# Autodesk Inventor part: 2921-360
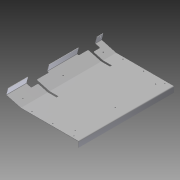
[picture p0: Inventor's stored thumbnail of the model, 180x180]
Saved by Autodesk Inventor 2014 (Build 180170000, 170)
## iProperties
Company: NHTSA/VRTC
Created: 2012-02
Part Number: 2921-360
Project: CHILD SIDE IMPACT SLED
Material: Steel
Description: BENCH SEAT PANEL
Document SubType Name: Modeling
Designer: Mike Vanvoorhis
Mass: 10084.5 g
Surface Area: 8157.07 cm^2
Volume: 1284.64 cm^3
Density: 7.85 g/cm^3
Appearance: Steel
Stock Number: PL 3.2 (1/8") x 614.5 (24 3/16") x 693 (27 5/16")
Title: Bench Seat Panel
Subject: Child Side Impact Sled
Author: Dave Walker
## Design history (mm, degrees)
sketch "Sketch1"
  geometry: L1 (417.373, -41)-(420.573, -41); L2 (420.573, -41)-(420.573, -6.4); L3 (417.373, -6.4)-(417.373, -41); L4 (-0.427, -3.2)-(414.173, -3.2); L5 (0, 0)-(-102.941, 27.969); L6 (-105.19, 31.896)-(-93.759, 73.97); L7 (-93.759, 73.97)-(-96.847, 74.809); L8 (-96.847, 74.809)-(-108.278, 32.735); L9 (-103.78, 24.88)-(-0.427, -3.2); L10 (414.173, 0)-(0, 0); L11 (0, 97.971)-(0, -64.162) reference; L12 (-216.266, 0)-(528.259, 0) reference; A1 r 3.2 centre (-102.102, 31.057) between (-105.19, 31.896) and (-102.941, 27.969); A2 r 3.2 centre (414.173, -6.4) between (417.373, -6.4) and (414.173, -3.2); A3 r 6.4 centre (414.173, -6.4) between (420.573, -6.4) and (414.173, 0); A4 r 6.4 centre (-102.102, 31.057) between (-108.278, 32.735) and (-103.78, 24.88); 1 further point
  constraints: 20 end point, 8 point on circle, 8 tangent, 5 parallel, 4 centre point, 3 point on line, 2 equal radius, 2 horizontal, 2 perpendicular, 1 collinear
  dimensions: "d0" = 3.2 distance of L1.start L1.end; "d2" = 3.2 distance between parallel lines of L10 L4 (= d0); "d3" = 15.2 deg angle of L9 L4; "d4" = 3.2 distance between parallel lines of L9 L5 (= d0); "d5" = 3.2 distance between parallel lines of L6 L8 (= d0); "d6" = 41 distance between parallel lines of L1 L10; "d7" = 421 distance from line of L4.start L2; "d8" = 113.5 distance from line of L4.start L8; "d9" = 50 distance between parallel lines of L7 L9; "d11" = 6.4 radius of A3; "d48" = 3.2 radius of A1
extrude "Extrusion1" new body sketch "Sketch1" stored distance "d12" = 693; taper "d13" = 0 deg
sketch "Sketch2"
  geometry: L1 (-3.2, 693)-(-3.2, 0) reference; L2 (-3.2, 598)-(171.8, 598); L3 (171.8, 598)-(171.8, 584); L4 (171.8, 584)-(-3.2, 584); L5 (-3.2, 584)-(-3.2, 598); L6 (-3.2, 209)-(171.8, 209); L7 (171.8, 209)-(171.8, 195); L8 (171.8, 195)-(-3.2, 195); L9 (-3.2, 195)-(-3.2, 209); 1 further point
  constraints: 16 end point, 4 parallel, 2 horizontal, 2 perpendicular, 2 point on line, 1 collinear
  dimensions: "d14" = 95 distance from line of L2 L1.start; "d15" = 14 distance between parallel lines of L4 L2; "d16" = 375 distance between parallel lines of L6 L4; "d17" = 14 distance between parallel lines of L8 L6 (= d15); "d18" = 175 distance between parallel lines of L3 L1
extrude "Extrusion2" cut sketch "Sketch2" stored distance "d19" = 700; taper "d20" = 0 deg
sketch "Sketch3"
  geometry: L1 (0, 0)-(414.173, 0) reference; L2 (420.573, 693)-(420.573, 0) reference; L3 (420.573, 693)-(420.573, 0) reference; 11 further points
  constraints: 5 vertical alignment, 4 horizontal alignment
  dimensions: "d25" = 15.5 distance from line of point (369.673, 15.5) L1; "d105" = 54 distance from line of point (340.573, 54) L1; "d106" = 346.5 distance from line of point (340.573, 346.5) L1; "d107" = 639 distance from line of point (340.573, 639) L1; "d108" = 677.5 distance from line of point (369.673, 677.5) L1; "d109" = 50.9 distance from line of point (369.673, 15.5) L2; "d110" = 205 distance from line of point (215.573, 15.5) L2; "d111" = 356 distance from line of point (64.573, 15.5) L2; "d112" = 80 distance from line of point (340.573, 639) L2
hole "Hole1" sketch "Sketch3" at (369.673, 15.5), (340.573, 54), (215.573, 15.5), (64.573, 15.5), (340.573, 346.5), (369.673, 677.5), (340.573, 639), (215.573, 677.5), (64.573, 677.5) diameter "d30" = 7.1374; stored, may be unused: countersink angle "d34" = 90 deg, drill point angle "d36" = 118 deg; dims "d31" = 6, "d32" = 4, "d33" = 2, "d35" = 8
sketch "Sketch4"
  geometry: L1 (195, 0)-(195, 43.6) reference; L2 (-498, 43.6)-(-498, 0) reference; L3 (0, 43.6)-(195, 43.6) reference; 7 further points; 4 other entities
  constraints: 2 vertical alignment, 1 horizontal alignment, 4 other
  dimensions: "d39" = 15 distance from line of point (179.5, 28.6) L3
hole "Hole2" sketch "Sketch4" at (179.5, 28.6), (-482.5, 28.6) diameter "d40" = 7.1374; stored, may be unused: countersink angle "d44" = 90 deg, drill point angle "d46" = 118 deg; dims "d41" = 6, "d42" = 4, "d43" = 2, "d45" = 3.2
fillet "Fillet1" dims "d49" = 5.76
fillet "Fillet2" dims "d50" = 7.94
sketch "Sketch17"
  geometry: L1 (0, 195)-(40, 195); L2 (40, 195)-(40, 145); L3 (40, 145)-(0, 145); L4 (0, 145)-(0, 195); 2 further points
  constraints: 8 end point, 2 parallel, 1 horizontal, 1 perpendicular
  dimensions: "d88" = 145 distance from line of L3 point (0, 0); "d89" = 40 distance of L2.end L3.end
extrude "Extrusion15" cut sketch "Sketch17" stored distance "d91" = 10; taper "d92" = 0 deg
sketch "Sketch18"
  geometry: L1 (-3.2, 375)-(-3.2, 0) reference; L2 (-3.2, 0)-(11.8, 0); L3 (11.8, 0)-(11.8, 90); L4 (11.8, 90)-(-3.2, 90); L5 (-3.2, 90)-(-3.2, 0); 1 further point
  constraints: 8 end point, 2 parallel, 1 horizontal, 1 perpendicular
  dimensions: "d93" = 90 distance from line of L4 L1.end; "d94" = 15 distance between parallel lines of L3 L1
extrude "Extrusion16" cut sketch "Sketch18" stored distance "d95" = 10; taper "d96" = 0 deg
sketch "Sketch19"
  geometry: L1 (-3.2, 95)-(-3.2, 0) reference; L2 (-3.2, 0)-(36.8, 0); L3 (36.8, 0)-(36.8, 50); L4 (36.8, 50)-(-3.2, 50); L5 (-3.2, 50)-(-3.2, 0); 1 further point
  constraints: 8 end point, 2 parallel, 1 horizontal, 1 perpendicular
  dimensions: "d97" = 45 distance from line of L4 L1.start; "d98" = 40 distance between parallel lines of L3 L1
extrude "Extrusion17" cut sketch "Sketch19" stored distance "d99" = 10; taper "d100" = 0 deg
sketch "Sketch20"
  geometry: L1 (-3.2, 285)-(-3.2, 0) reference; L2 (-3.2, 285)-(11.8, 285); L3 (11.8, 285)-(11.8, 215); L4 (11.8, 215)-(-3.2, 215); L5 (-3.2, 215)-(-3.2, 285); L6 (109.104, 285)-(3.2, 285) reference; 1 further point
  constraints: 8 end point, 2 parallel, 1 horizontal, 1 perpendicular
  dimensions: "d101" = 70 distance between parallel lines of L4 L6; "d102" = 15 distance between parallel lines of L3 L1
extrude "Extrusion18" cut sketch "Sketch20" stored distance "d103" = 0; taper "d104" = 0 deg
fillet "Fillet3" dims "d113" = 6
sketch "Sketch21"
  geometry: L1 (-109.104, 0)-(-109.104, 145) reference; 7 further points; 3 other entities
  constraints: 3 horizontal alignment, 2 vertical alignment, 3 other
  dimensions: "d114" = 68.5 distance from line of point (-40.604, 54) L1
hole "Hole3" sketch "Sketch21" at (-40.604, 54), (-40.604, 639), (-40.604, 346.5) diameter "d115" = 7.14375; stored, may be unused: countersink angle "d119" = 90 deg, drill point angle "d121" = 118 deg; dims "d116" = 6, "d117" = 4, "d118" = 2, "d120" = 8
body "Solid1"
node "Projected Loop1"
node "Projected Loop2"
node "Projected Loop3"
other parameters: "d1" = 3.2 (= d0)
